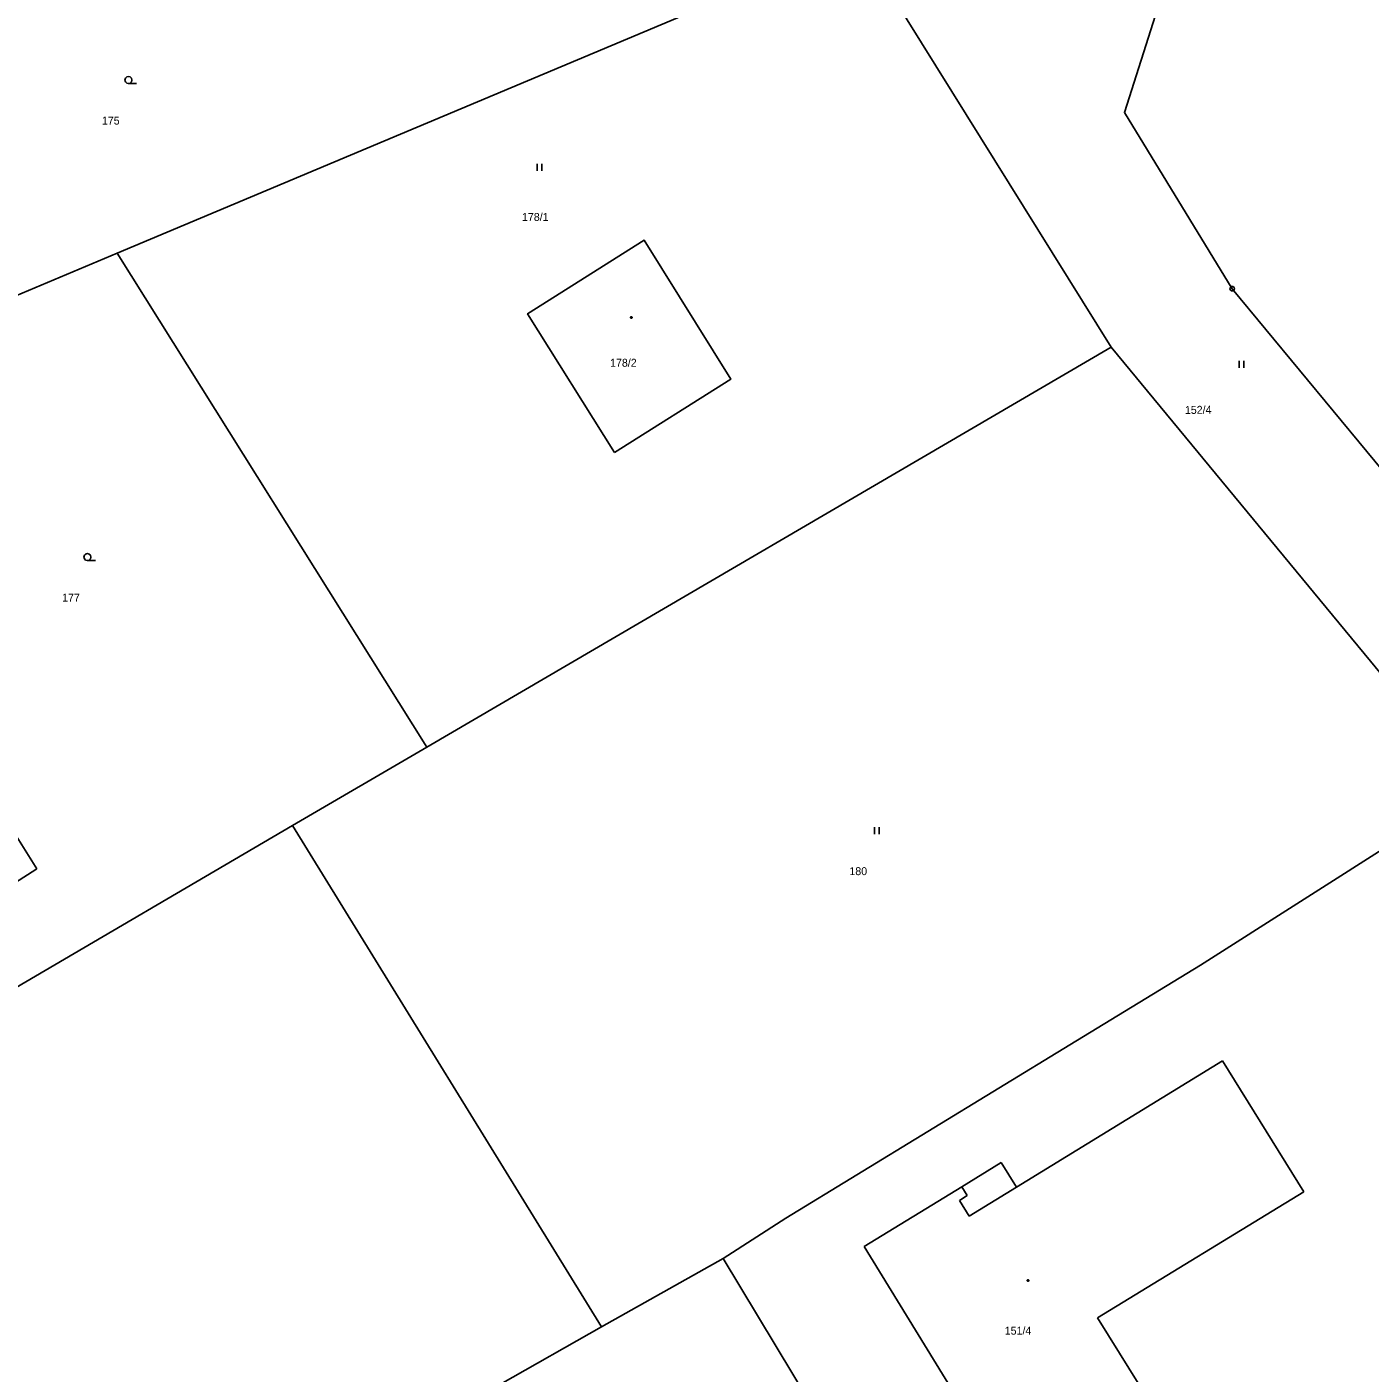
# Model space of a CAD drawing. Extents: x -871430 to -870620, y -1010094 to -1009649.
# Drawn here: x -870895.2 to -870823.3, y -1010013.9 to -1009941.8 of the extents above; entities that cross this region are included whole.
import ezdxf

# ---------------------------------------------------------------- set-up
doc = ezdxf.new("R2010")
doc.units = 0
for name, color, linetype in [('Vrstva 1', 7, 'Continuous'), ('Vrstva 2', 7, 'Continuous'), ('Vrstva 3', 7, 'Continuous'), ('Vrstva 4', 7, 'Continuous'), ('Vrstva 5', 7, 'Continuous'), ('Vrstva 8', 7, 'Continuous')]:
    doc.layers.add(name, color=color, linetype=linetype)

msp = doc.modelspace()

# ---------------------------------------------------------------- linework, layer by layer
at = {"layer": 'Vrstva 1'}
for p, q in [((-870850.67, -1009937.26), (-870890.37, -1009953.94)), ((-870837.15, -1009958.98), (-870850.67, -1009937.26)), ((-870890.37, -1009953.94), (-870910.17, -1009962.26)), ((-870890.37, -1009953.94), (-870873.8, -1009980.41)), ((-870816.41, -1009973.1), (-870830.66, -1009955.85)), ((-870873.8, -1009980.41), (-870837.15, -1009958.98)), ((-870817.46, -1009982.83), (-870837.15, -1009958.98)), ((-870904.48, -1009971.34), (-870894.67, -1009986.93)), ((-870880.98, -1009984.61), (-870873.8, -1009980.41)), ((-870903.67, -1009997.88), (-870880.98, -1009984.61)), ((-870880.98, -1009984.61), (-870864.43, -1010011.46)), ((-870820.29, -1009984.39), (-870832.36, -1009992.09)), ((-870894.67, -1009986.93), (-870919.7, -1010002.73)), ((-870832.36, -1009992.09), (-870839.36, -1009996.35)), ((-870839.36, -1009996.35), (-870854.57, -1010005.64)), ((-870842.22, -1010003.97), (-870831.18, -1009997.21)), ((-870831.18, -1009997.21), (-870826.83, -1010004.22)), ((-870845.14, -1010003.95), (-870843.03, -1010002.66)), ((-870843.03, -1010002.66), (-870842.22, -1010003.97)), ((-870850.37, -1010007.15), (-870845.14, -1010003.95)), ((-870826.83, -1010004.22), (-870837.87, -1010010.98)), ((-870854.57, -1010005.64), (-870857.92, -1010007.79)), ((-870840.12, -1010023.87), (-870850.37, -1010007.15)), ((-870857.92, -1010007.79), (-870864.43, -1010011.46)), ((-870857.92, -1010007.79), (-870849.45, -1010021.86)), ((-870837.87, -1010010.98), (-870834.73, -1010016.02)), ((-870864.43, -1010011.46), (-870869.85, -1010014.52))]:
    msp.add_line(p, q, dxfattribs=at)
for points in [[(-870830.66, -1009955.85), (-870836.43, -1009946.41), (-870833.62, -1009937.6), (-870794.48, -1009920.9)], [(-870863.75, -1009964.63), (-870857.51, -1009960.69), (-870862.16, -1009953.25), (-870868.4, -1009957.19), (-870863.75, -1009964.63)]]:
    msp.add_lwpolyline(points, dxfattribs=at)
at = {"layer": 'Vrstva 3'}
for p, q in [((-870867.885, -1009949.155), (-870867.885, -1009949.53)), ((-870867.635, -1009949.53), (-870867.635, -1009949.155)), ((-870830.295, -1009959.715), (-870830.295, -1009960.09)), ((-870830.045, -1009960.09), (-870830.045, -1009959.715)), ((-870849.825, -1009984.685), (-870849.825, -1009985.06)), ((-870849.575, -1009985.06), (-870849.575, -1009984.685))]:
    msp.add_line(p, q, dxfattribs=at)
for points in [[(-870889.77, -1009944.86), (-870889.865, -1009944.835), (-870889.932, -1009944.765), (-870889.958, -1009944.672), (-870889.932, -1009944.58), (-870889.865, -1009944.51), (-870889.77, -1009944.485), (-870889.675, -1009944.51), (-870889.608, -1009944.58), (-870889.582, -1009944.672), (-870889.608, -1009944.765), (-870889.675, -1009944.835), (-870889.77, -1009944.86), (-870889.332, -1009944.86)], [(-870891.97, -1009970.41), (-870892.065, -1009970.385), (-870892.132, -1009970.315), (-870892.158, -1009970.222), (-870892.132, -1009970.13), (-870892.065, -1009970.06), (-870891.97, -1009970.035), (-870891.875, -1009970.06), (-870891.808, -1009970.13), (-870891.782, -1009970.222), (-870891.808, -1009970.315), (-870891.875, -1009970.385), (-870891.97, -1009970.41), (-870891.532, -1009970.41)]]:
    msp.add_lwpolyline(points, dxfattribs=at)
at = {"layer": 'Vrstva 4'}
for p, q in [((-870844.85, -1010004.42), (-870845.27, -1010004.68)), ((-870845.14, -1010003.95), (-870844.85, -1010004.42)), ((-870844.74, -1010005.53), (-870842.22, -1010003.97)), ((-870845.27, -1010004.68), (-870844.74, -1010005.53))]:
    msp.add_line(p, q, dxfattribs=at)
at = {"layer": 'Vrstva 5'}
for points in [[(-870862.84, -1009957.348), (-870862.815, -1009957.352), (-870862.802, -1009957.375), (-870862.798, -1009957.39), (-870862.802, -1009957.412), (-870862.822, -1009957.43), (-870862.84, -1009957.432), (-870862.862, -1009957.425), (-870862.878, -1009957.41), (-870862.882, -1009957.39), (-870862.878, -1009957.368), (-870862.857, -1009957.35), (-870862.84, -1009957.348)], [(-870841.6, -1010008.928), (-870841.575, -1010008.932), (-870841.562, -1010008.955), (-870841.558, -1010008.97), (-870841.562, -1010008.992), (-870841.582, -1010009.01), (-870841.6, -1010009.012), (-870841.622, -1010009.005), (-870841.638, -1010008.99), (-870841.642, -1010008.97), (-870841.638, -1010008.948), (-870841.617, -1010008.93), (-870841.6, -1010008.928)]]:
    msp.add_lwpolyline(points, dxfattribs=at)
at = {"layer": 'Vrstva 8'}
msp.add_line((-870830.672, -1009955.85), (-870830.648, -1009955.85), dxfattribs=at)
msp.add_lwpolyline([(-870830.622, -1009955.73), (-870830.56, -1009955.778), (-870830.535, -1009955.85), (-870830.56, -1009955.922), (-870830.622, -1009955.97), (-870830.698, -1009955.97), (-870830.76, -1009955.922), (-870830.785, -1009955.85), (-870830.76, -1009955.778), (-870830.698, -1009955.73), (-870830.622, -1009955.73)], dxfattribs=at)

# ---------------------------------------------------------------- texts
at = {"layer": 'Vrstva 2'}
for s, p in [('175', (-870891.192, -1009947.06)), ('178/1', (-870868.695, -1009952.22)), ('178/2', (-870863.977, -1009960.03)), ('177', (-870893.322, -1009972.61)), ('180', (-870851.162, -1009987.26)), ('151/4', (-870842.843, -1010011.87))]:
    msp.add_text(s, height=0.425, dxfattribs=at).set_placement(p)
msp.add_text('152/4', height=0.425, rotation=0.63025, dxfattribs=at).set_placement((-870833.192, -1009962.559))

doc.saveas('drawing.dxf')
